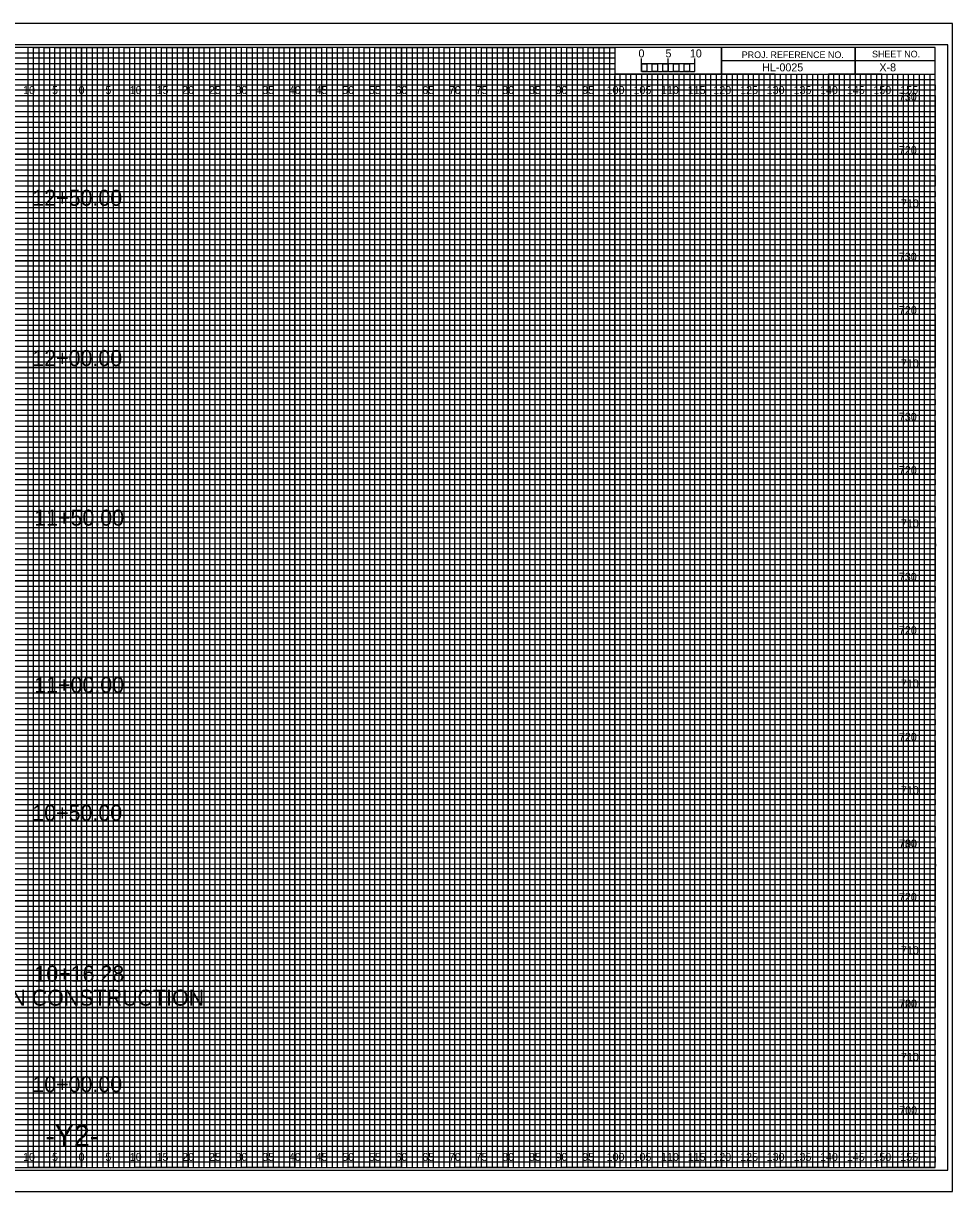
# Model space of a CAD drawing. Extents: x -13 to 323, y -5 to 654.
# Drawn here: x 149.1 to 323.3, y -4.5 to 214.5 of the extents above; entities that cross this region are included whole.
import ezdxf

# ---------------------------------------------------------------- set-up
doc = ezdxf.new("R2010")
doc.units = 0
for name, color, linetype in [('Exist CMT Pavement', 7, 'Continuous'), ('Exist Cross Section Cell', 7, 'Continuous'), ('Exist XS Center Line Elevation Label', 7, 'Continuous'), ('Exist XS Ground Line', 7, 'Continuous'), ('Prop CMT Pvmt Course 1', 7, 'Continuous'), ('Prop CMT Pvmt Course 1 Wedge', 7, 'Continuous'), ('Prop CMT Pvmt Course 2', 7, 'Continuous'), ('Prop CMT Pvmt Course 3', 7, 'Continuous'), ('Prop CMT Pvmt Surface', 7, 'Continuous'), ('Prop CMT Pvmt Surface Shoulder', 7, 'Continuous'), ('Prop CMT Pvmt Wedge Surface 1', 7, 'Continuous'), ('Prop CMT Shld Paved Course 1', 7, 'Continuous'), ('Prop CMT Shld Paved Course 2', 7, 'Continuous'), ('Prop CMT Shld Paved Course 3', 7, 'Continuous'), ('Prop CMT Slope Grass', 7, 'Continuous'), ('Prop CMT Subgrade Earthwork', 7, 'Continuous'), ('Scratch_Level_1', 7, 'Continuous')]:
    doc.layers.add(name, color=color, linetype=linetype)

msp = doc.modelspace()

# ---------------------------------------------------------------- linework, layer by layer
at = {"layer": 'Exist XS Center Line Elevation Label'}
for points in [[(145, 0), (155, 0), (155, 210), (165, 210), (165, 0), (175, 0), (175, 210), (185, 210), (185, 0), (195, 0), (195, 210), (205, 210), (205, 0), (215, 0), (215, 210), (225, 210), (225, 0), (235, 0), (235, 210), (245, 210), (245, 0), (255, 0), (255, 210), (259.93, 210), (260, 210), (260, 205), (264.99, 205), (264.99, 0), (275, 0), (275, 205), (285, 205), (285, 0), (295, 0), (295, 205), (305, 205), (305, 0), (315, 0), (315, 205)], [(0, 205), (275, 205)], [(0, 185), (320, 185), (320, 195), (0, 195)], [(0, 165), (320, 165), (320, 175), (0, 175)], [(0, 145), (320, 145), (320, 155), (0, 155)], [(0, 125), (320, 125), (320, 135), (0, 135)], [(0, 105), (320, 105), (320, 115), (0, 115)], [(0, 85), (320, 85), (320, 95), (0, 95)], [(0, 65), (320, 65), (320, 75), (0, 75)], [(0, 45), (320, 45), (320, 55), (0, 55)], [(0, 25), (320, 25), (320, 35), (0, 35)], [(0, 5), (320, 5), (320, 15), (0, 15)]]:
    msp.add_lwpolyline(points, dxfattribs=at)
at = {"layer": 'Exist XS Ground Line'}
for p, q in [((150, 210), (140, 210)), ((150, 0), (150, 210)), ((170, 210), (160, 210)), ((160, 210), (160, 0)), ((170, 0), (170, 210)), ((190, 210), (180, 210)), ((180, 210), (180, 0)), ((190, 0), (190, 210)), ((210, 210), (200, 210)), ((200, 210), (200, 0)), ((210, 0), (210, 210)), ((230, 210), (220, 210)), ((220, 210), (220, 0)), ((230, 0), (230, 210)), ((250, 210), (240, 210)), ((240, 210), (240, 0)), ((250, 0), (250, 210)), ((260, 210), (260, 0)), ((270, 0), (270, 205)), ((290, 205), (280, 205)), ((280, 205), (280, 0)), ((290, 0), (290, 205)), ((310, 205), (300, 205)), ((300, 205), (300, 0)), ((310, 0), (310, 205)), ((160, 0), (150, 0)), ((180, 0), (170, 0)), ((200, 0), (190, 0)), ((220, 0), (210, 0)), ((240, 0), (230, 0)), ((260, 0), (250, 0)), ((280, 0), (270, 0)), ((300, 0), (290, 0)), ((320, 0), (310, 0)), ((320, 0), (320, 0))]:
    msp.add_line(p, q, dxfattribs=at)
for points in [[(0, 200), (320, 200), (320, 190), (0, 190)], [(0, 180), (320, 180), (320, 170), (0, 170)], [(0, 160), (320, 160), (320, 150), (0, 150)], [(0, 140), (320, 140), (320, 130), (0, 130)], [(0, 120), (320, 120), (320, 110), (0, 110)], [(0, 100), (320, 100), (320, 90), (0, 90)], [(0, 80), (320, 80), (320, 70), (0, 70)], [(0, 60), (320, 60), (320, 50), (0, 50)], [(0, 40), (320, 40), (320, 30), (0, 30)], [(0, 20), (320, 20), (320, 10), (0, 10)]]:
    msp.add_lwpolyline(points, dxfattribs=at)
at = {"layer": 'Prop CMT Pvmt Course 2'}
msp.add_lwpolyline([(-13.4, -4.5), (323.3, -4.5), (323.3, 214.5), (-13.4, 214.5)], close=True, dxfattribs=at)
at = {"layer": 'Prop CMT Pvmt Course 3'}
msp.add_lwpolyline([(-10.8, -0.5), (322.4, -0.5), (322.4, 210.5), (-10.8, 210.5)], close=True, dxfattribs=at)
msp.add_lwpolyline([(-10.8, -0.5), (322.4, -0.5), (322.4, 210.5), (-10.8, 210.5)], close=True, dxfattribs=at)
at = {"layer": 'Prop CMT Pvmt Surface'}
for p, q in [((323.3, 214.5), (-13.4, 214.5)), ((323.3, 214.5), (-13.4, 214.5)), ((-13.4, -4.5), (323.3, -4.5)), ((-13.4, -4.5), (323.3, -4.5))]:
    msp.add_line(p, q, dxfattribs=at)
at = {"layer": 'Prop CMT Shld Paved Course 1'}
for p, q in [((305, 210), (305, 205)), ((305, 205), (305, 210)), ((280, 207.5), (280, 205)), ((320, 207.49), (280, 207.49)), ((280, 205), (320, 205))]:
    msp.add_line(p, q, dxfattribs=at)
for points in [[(320, 210), (0, 210), (0, 0), (320, 0)], [(280, 210), (260, 210), (260, 205.03), (280, 205.03)], [(320, 210), (280, 210), (280, 205), (320, 205)]]:
    msp.add_lwpolyline(points, close=True, dxfattribs=at)
at = {"layer": 'Prop CMT Shld Paved Course 2'}
for p, q in [((267, 205), (266.01, 205)), ((266.01, 205), (266.01, 0)), ((267, 0), (267, 205)), ((269, 205), (268, 205)), ((268, 205), (268, 0)), ((269, 0), (269, 205)), ((266.01, 0), (265, 0)), ((268, 0), (267, 0))]:
    msp.add_line(p, q, dxfattribs=at)
for points in [[(150, 0), (151, 0), (151, 210), (152, 210), (152, 0)], [(152, 0), (153, 0), (153, 210), (154, 210), (154, 0)], [(155, 0), (156, 0), (156, 210), (157, 210), (157, 0)], [(157, 0), (158, 0), (158, 210), (159, 210), (159, 0)], [(160, 0), (161, 0), (161, 210), (162, 210), (162, 0)], [(162, 0), (163, 0), (163, 210), (164, 210), (164, 0)], [(165, 0), (166, 0), (166, 210), (167, 210), (167, 0)], [(167, 0), (168, 0), (168, 210), (169, 210), (169, 0)], [(170, 0), (171, 0), (171, 210), (172, 210), (172, 0)], [(172, 0), (173, 0), (173, 210), (174, 210), (174, 0)], [(175, 0), (176, 0), (176, 210), (177, 210), (177, 0)], [(177, 0), (178, 0), (178, 210), (179, 210), (179, 0)], [(180, 0), (181, 0), (181, 210), (182, 210), (182, 0)], [(182, 0), (183, 0), (183, 210), (184, 210), (184, 0)], [(185, 0), (186, 0), (186, 210), (187, 210), (187, 0)], [(187, 0), (188, 0), (188, 210), (189, 210), (189, 0)], [(190, 0), (191, 0), (191, 210), (192, 210), (192, 0)], [(192, 0), (193, 0), (193, 210), (194, 210), (194, 0)], [(195, 0), (196, 0), (196, 210), (197, 210), (197, 0)], [(197, 0), (198, 0), (198, 210), (199, 210), (199, 0)], [(200, 0), (201, 0), (201, 210), (202, 210), (202, 0)], [(202, 0), (203, 0), (203, 210), (204, 210), (204, 0)], [(205, 0), (206, 0), (206, 210), (207, 210), (207, 0)], [(207, 0), (208, 0), (208, 210), (209, 210), (209, 0)], [(210, 0), (211, 0), (211, 210), (212, 210), (212, 0)], [(212, 0), (213, 0), (213, 210), (214, 210), (214, 0)], [(215, 0), (216, 0), (216, 210), (217, 210), (217, 0)], [(217, 0), (218, 0), (218, 210), (219, 210), (219, 0)], [(220, 0), (221, 0), (221, 210), (222, 210), (222, 0)], [(222, 0), (223, 0), (223, 210), (224, 210), (224, 0)], [(225, 0), (226, 0), (226, 210), (227, 210), (227, 0)], [(227, 0), (228, 0), (228, 210), (229, 210), (229, 0)], [(230, 0), (231, 0), (231, 210), (232, 210), (232, 0)], [(232, 0), (233, 0), (233, 210), (234, 210), (234, 0)], [(235, 0), (236, 0), (236, 210), (237, 210), (237, 0)], [(237, 0), (238, 0), (238, 210), (239, 210), (239, 0)], [(240, 0), (241, 0), (241, 210), (242, 210), (242, 0)], [(242, 0), (243, 0), (243, 210), (244, 210), (244, 0)], [(245, 0), (246, 0), (246, 210), (247, 210), (247, 0)], [(247, 0), (248, 0), (248, 210), (249, 210), (249, 0)], [(250, 0), (251, 0), (251, 210), (252, 210), (252, 0)], [(252, 0), (253, 0), (253, 210), (254, 210), (254, 0)], [(255, 0), (256, 0), (256, 210), (257, 210), (257, 0)], [(257, 0), (258, 0), (258, 210), (259, 210), (259, 0)], [(260, 0), (261, 0), (261, 205), (262.02, 205), (262.02, 0)], [(262, 0), (263, 0), (263, 205), (263.99, 205), (263.99, 0)], [(270, 0), (270.98, 0), (270.98, 205), (272, 205), (272, 0)], [(272, 0), (273, 0), (273, 205), (274.05, 205), (274.05, 0)], [(275, 0), (276, 0), (276, 205), (277, 205), (277, 0)], [(277, 0), (278, 0), (278, 205), (279, 205), (279, 0)], [(280, 0), (281, 0), (281, 205), (282, 205), (282, 0)], [(282, 0), (283, 0), (283, 205), (284, 205), (284, 0)], [(285, 0), (286, 0), (286, 205), (287, 205), (287, 0)], [(287, 0), (288, 0), (288, 205), (289, 205), (289, 0)], [(290, 0), (291, 0), (291, 205), (292, 205), (292, 0)], [(292, 0), (293, 0), (293, 205), (294, 205), (294, 0)], [(295, 0), (296, 0), (296, 205), (297, 205), (297, 0)], [(297, 0), (298, 0), (298, 205), (299, 205), (299, 0)], [(300, 0), (301, 0), (301, 205), (302, 205), (302, 0)], [(302, 0), (303, 0), (303, 205), (304, 205), (304, 0)], [(305, 0), (306, 0), (306, 205), (307, 205), (307, 0)], [(307, 0), (308, 0), (308, 205), (309, 205), (309, 0)], [(310, 0), (311, 0), (311, 205), (312, 205), (312, 0)], [(312, 0), (313, 0), (313, 205), (314, 205), (314, 0)], [(315, 0), (316, 0), (316, 205), (317, 205), (317, 0)], [(317, 0), (318, 0), (318, 205), (319, 205), (319, 0)]]:
    msp.add_lwpolyline(points, dxfattribs=at)
at = {"layer": 'Prop CMT Shld Paved Course 3'}
for p, q in [((265, 205.49), (265, 207.9)), ((265, 206.9), (265, 207.9)), ((270, 205.49), (270, 207.9)), ((275, 205.49), (275, 207.9)), ((275, 206.9), (275, 207.9))]:
    msp.add_line(p, q, dxfattribs=at)
for points in [[(275, 206.9), (265, 206.9), (265, 205.49), (275, 205.49)], [(265, 206.9), (266, 206.9), (266, 205.49), (265, 205.49)], [(267, 206.9), (268, 206.9), (268, 205.49), (267, 205.49)], [(269, 206.9), (270, 206.9), (270, 205.49), (269, 205.49)], [(271, 206.9), (272, 206.9), (272, 205.49), (271, 205.49)], [(273, 206.9), (274, 206.9), (274, 205.49), (273, 205.49)]]:
    msp.add_lwpolyline(points, close=True, dxfattribs=at)
at = {"layer": 'Prop CMT Subgrade Earthwork'}
for p, q in [((150, 0), (150, 210)), ((150, 0), (150, 210)), ((160, 0), (160, 210)), ((160, 0), (160, 210)), ((170, 0), (170, 210)), ((170, 0), (170, 210)), ((180, 0), (180, 210)), ((180, 0), (180, 210)), ((190, 0), (190, 210)), ((190, 0), (190, 210)), ((200, 0), (200, 210)), ((200, 0), (200, 210)), ((210, 0), (210, 210)), ((210, 0), (210, 210)), ((220, 0), (220, 210)), ((220, 0), (220, 210)), ((230, 0), (230, 210)), ((230, 0), (230, 210)), ((240, 0), (240, 210)), ((240, 0), (240, 210)), ((250, 0), (250, 210)), ((250, 0), (250, 210)), ((260, 0), (260, 204.69)), ((260, 0), (260, 204.69)), ((270, 0), (270, 204.69)), ((270, 0), (270, 204.69)), ((280, 0), (280, 204.69)), ((280, 0), (280, 204.69)), ((290, 0), (290, 204.69)), ((290, 0), (290, 204.69)), ((300, 0), (300, 204.69)), ((300, 0), (300, 204.69)), ((310, 0), (310, 204.69)), ((310, 0), (310, 204.69)), ((0, 200), (320, 200)), ((0, 200), (320, 200)), ((0, 190), (320, 190)), ((0, 190), (320, 190)), ((0, 180), (320, 180)), ((0, 180), (320, 180)), ((0, 170), (320, 170)), ((0, 170), (320, 170)), ((0, 160), (320, 160)), ((0, 160), (320, 160)), ((0, 150), (320, 150)), ((0, 150), (320, 150)), ((0, 140), (320, 140)), ((0, 140), (320, 140)), ((0, 130), (320, 130)), ((0, 130), (320, 130)), ((0, 120), (320, 120)), ((0, 120), (320, 120)), ((0, 110), (320, 110)), ((0, 110), (320, 110)), ((0, 100), (320, 100)), ((0, 100), (320, 100)), ((0, 90), (320, 90)), ((0, 90), (320, 90)), ((0, 80), (320, 80)), ((0, 80), (320, 80)), ((0, 70), (320, 70)), ((0, 70), (320, 70)), ((0, 60), (320, 60)), ((0, 60), (320, 60)), ((0, 50), (320, 50)), ((0, 50), (320, 50)), ((0, 40), (320, 40)), ((0, 40), (320, 40)), ((0, 30), (320, 30)), ((0, 30), (320, 30)), ((0, 20), (320, 20)), ((0, 20), (320, 20)), ((0, 10), (320, 10)), ((0, 10), (320, 10))]:
    msp.add_line(p, q, dxfattribs=at)
at = {"layer": 'Scratch_Level_1'}
for p, q in [((0, 209), (260, 209)), ((260, 209), (260, 207.98)), ((260, 207.98), (0, 207.98)), ((0, 207), (260, 207)), ((260, 205.89), (0, 205.89)), ((260, 207), (260, 205.89)), ((0, 204), (320, 204))]:
    msp.add_line(p, q, dxfattribs=at)
for points in [[(0, 203), (270, 203), (320, 203), (320, 202), (0, 202)], [(0, 201), (320, 201), (320, 199), (0, 199)], [(0, 198), (320, 198), (320, 197), (0, 196.98)], [(0, 196), (320, 196), (320, 194), (0, 194)], [(0, 193), (320, 193), (320, 192), (0, 192)], [(0, 191), (320, 191), (320, 189), (0, 189)], [(0, 188), (320, 188), (320, 187), (0, 187)], [(0, 186), (320, 186), (320, 184), (0, 184)], [(0, 183), (320, 183), (320, 182), (0, 182)], [(0, 181), (320, 181), (320, 179), (0, 179)], [(0, 178), (320, 178), (320, 177), (0, 177)], [(0, 176), (320, 176), (320, 173.95), (320, 173), (320, 172), (0, 172)], [(0, 174), (320, 174), (320, 173), (0, 173)], [(0, 171), (320, 171), (320, 169), (0, 169.03)], [(0, 169.03), (320, 169), (320, 168), (0, 168)], [(0, 167), (320, 167), (320, 166), (0, 166)], [(0, 164), (320, 164), (320, 163), (0, 163)], [(0, 162), (320, 162), (320, 161), (0, 161)], [(-0.07, 158.89), (320, 158.89), (320, 157.88), (-0.07, 157.88)], [(0, 157), (320, 157), (320, 156), (0, 156)], [(0, 154), (320, 154), (320, 153), (0, 153)], [(0, 152), (320, 152), (320, 151), (0, 151)], [(0, 149), (320, 149), (320, 148), (0, 148)], [(0, 147), (320, 147), (320, 146), (0, 146)], [(0, 144), (320, 144), (320, 143), (0, 143)], [(0, 142), (320, 142), (320, 141), (0, 141)], [(0, 139), (320, 139), (319.99, 137.98), (0, 138)], [(0, 137), (320, 137), (320, 136), (0, 136)], [(0, 134), (320, 134), (320, 133), (0, 133)], [(0, 132), (320, 132), (320, 131), (0, 131)], [(0, 129), (320, 129), (320, 128), (0, 128)], [(0, 127), (320, 127), (320, 126), (0, 126)], [(0, 124), (320, 124), (320, 123), (0, 123)], [(0, 122), (320, 122), (320, 121), (0, 121)], [(0, 119), (320, 119), (320, 118), (0, 118)], [(0, 116.99), (320.07, 116.91), (320, 116), (0, 116)], [(0, 114), (320, 114), (320, 113), (0, 113)], [(0, 112), (320, 112), (320, 111), (0, 111)], [(0, 109), (320, 109), (320, 108), (0, 108)], [(0, 107), (320, 107), (320, 106), (0, 106)], [(0, 104), (320, 104), (320, 103), (0, 103)], [(0, 102), (320, 102), (320, 101), (0, 101)], [(0, 99), (320, 99), (320, 98), (0, 98)], [(0, 97), (320, 97), (320, 96), (0, 96)], [(0, 94), (320, 94), (320, 93), (0, 93)], [(0, 92), (320, 92), (320, 91), (0, 91)], [(0, 89), (320, 89), (320, 88), (0, 88)], [(0, 87), (320, 87), (320, 86), (0, 86)], [(0, 84), (320, 84), (320, 83), (0, 83)], [(0, 82), (320, 82), (320, 81), (0, 81)], [(0, 79), (320, 79), (319.99, 77.98), (0, 78)], [(0, 77), (320, 77), (320, 76), (0, 76)], [(0, 74), (320, 74), (320, 73), (0, 73)], [(0, 72), (320, 72), (320, 71), (0, 71)], [(0, 69), (320, 69), (320, 68), (0, 68)], [(0, 67), (320, 67), (320, 66), (0, 66)], [(0, 64), (320, 64), (320, 63), (0, 63)], [(0, 62), (320, 62), (320, 61), (0, 61)], [(0, 59), (320, 59), (320, 58), (0, 58)], [(0, 56.99), (320.07, 56.91), (320, 56), (0, 56)], [(0, 54), (320, 54), (320, 53), (0, 53)], [(0, 52), (320, 52), (320, 51), (0, 51)], [(0, 49), (320, 49), (320, 48), (0, 48)], [(0, 47), (320, 47), (320, 46), (0, 46)], [(0, 44), (320, 44), (320, 43), (0, 43)], [(0, 42), (320, 42), (320, 41), (0, 41)], [(0, 39), (320, 39), (320, 38), (0, 38)], [(0, 37), (320, 37), (320, 36), (0, 36)], [(0, 34), (320, 34), (320, 33), (0, 33)], [(0, 32), (320, 32), (320, 31), (0, 31)], [(0, 29), (320, 29), (320, 28), (0, 28)], [(0, 27), (320, 27), (320, 26), (0, 26)], [(0, 24), (320, 24), (320, 23), (0, 23)], [(0, 22), (320, 22), (320, 21), (0, 21)], [(0, 19), (320, 19), (320, 18), (0, 18)], [(0, 17), (320, 17), (320, 16), (0, 16)], [(0, 14), (320, 14), (320, 13), (0, 13)], [(0, 12), (320, 12), (320, 11), (0, 11)], [(0, 9), (320, 9), (320, 8), (0, 8)], [(0, 7), (320, 7), (320, 6), (0, 6)], [(0, 4), (320, 4), (320, 3), (0, 3)], [(0, 2), (320, 2), (320, 1), (0, 1)]]:
    msp.add_lwpolyline(points, dxfattribs=at)

# ---------------------------------------------------------------- texts
at = {"layer": 'Exist CMT Pavement'}
msp.add_text('-Y2-', height=4, dxfattribs=at).set_placement((153.21, 4))
at = {"layer": 'Exist Cross Section Cell'}
for s, p in [('10', (149.04, 201.25)), ('5', (154.47, 201.25)), ('0', (159.45, 201.25)), ('0', (159.45, 201.25)), ('5', (164.47, 201.25)), ('10', (169.04, 201.25)), ('15', (174.06, 201.25)), ('20', (178.86, 201.25)), ('25', (183.88, 201.25)), ('30', (188.86, 201.25)), ('35', (193.88, 201.25)), ('40', (198.86, 201.25)), ('45', (203.88, 201.25)), ('50', (208.86, 201.25)), ('55', (213.88, 201.25)), ('60', (218.86, 201.25)), ('65', (223.88, 201.25)), ('70', (228.86, 201.25)), ('75', (233.88, 201.25)), ('80', (238.86, 201.25)), ('85', (243.88, 201.25)), ('90', (248.86, 201.25)), ('95', (253.88, 201.25)), ('100', (258.44, 201.25)), ('105', (263.47, 201.25)), ('110', (268.62, 201.25)), ('115', (273.65, 201.25)), ('120', (278.44, 201.25)), ('125', (283.47, 201.25)), ('130', (288.44, 201.25)), ('135', (293.47, 201.25)), ('140', (298.44, 201.25)), ('145', (303.47, 201.25)), ('150', (308.44, 201.25)), ('155', (313.47, 201.25)), ('10', (149.04, 1.25)), ('5', (154.47, 1.25)), ('0', (159.45, 1.25)), ('0', (159.45, 1.25)), ('5', (164.47, 1.25)), ('10', (169.04, 1.25)), ('15', (174.06, 1.25)), ('20', (178.86, 1.25)), ('25', (183.88, 1.25)), ('30', (188.86, 1.25)), ('35', (193.88, 1.25)), ('40', (198.86, 1.25)), ('45', (203.88, 1.25)), ('50', (208.86, 1.25)), ('55', (213.88, 1.25)), ('60', (218.86, 1.25)), ('65', (223.88, 1.25)), ('70', (228.86, 1.25)), ('75', (233.88, 1.25)), ('80', (238.86, 1.25)), ('85', (243.88, 1.25)), ('90', (248.86, 1.25)), ('95', (253.88, 1.25)), ('100', (258.44, 1.25)), ('105', (263.47, 1.25)), ('110', (268.62, 1.25)), ('115', (273.65, 1.25)), ('120', (278.44, 1.25)), ('125', (283.47, 1.25)), ('130', (288.44, 1.25)), ('135', (293.47, 1.25)), ('140', (298.44, 1.25)), ('145', (303.47, 1.25)), ('150', (308.44, 1.25)), ('155', (313.47, 1.25))]:
    msp.add_text(s, height=1.5, dxfattribs=at).set_placement(p)
at = {"layer": 'Prop CMT Pvmt Course 1'}
for s, p in [('12+50.00', (150.77, 180.3)), ('12+00.00', (150.77, 150.26)), ('11+50.00', (151.13, 120.34)), ('11+00.00', (151.13, 89)), ('10+50.00', (150.77, 65.01)), ('10+16.28', (151.16, 34.86)), ('BEGIN CONSTRUCTION', (137.07, 30.36)), ('10+00.00', (150.77, 14.15))]:
    msp.add_text(s, height=3, dxfattribs=at).set_placement(p)
at = {"layer": 'Prop CMT Pvmt Course 1 Wedge'}
msp.add_text('HL-0025', height=1.5, dxfattribs=at).set_placement((287.6, 205.5))
at = {"layer": 'Prop CMT Pvmt Surface Shoulder'}
for s, p in [('730', (313.22, 200)), ('720', (313.23, 190)), ('710', (313.61, 180)), ('730', (313.22, 170)), ('720', (313.23, 160)), ('710', (313.61, 150)), ('730', (313.22, 140)), ('720', (313.23, 130)), ('710', (313.61, 120)), ('730', (313.22, 110)), ('720', (313.23, 100)), ('710', (313.61, 90)), ('720', (313.23, 80)), ('710', (313.61, 70)), ('730', (313.22, 60)), ('700', (313.28, 60)), ('720', (313.23, 50)), ('710', (313.61, 40)), ('720', (313.23, 30)), ('700', (313.28, 30)), ('710', (313.61, 20)), ('700', (313.28, 10))]:
    msp.add_text(s, height=1.5, dxfattribs=at).set_placement(p)
at = {"layer": 'Prop CMT Pvmt Wedge Surface 1'}
for s, p in [('5', (269.47, 208.12)), ('10', (274.04, 208.12))]:
    msp.add_text(s, height=1.5, dxfattribs=at).set_placement(p)
at = {"layer": 'Prop CMT Shld Paved Course 1'}
for s, p in [('PROJ. REFERENCE NO.', (283.77, 207.99)), ('SHEET NO.', (308.19, 208.12))]:
    msp.add_text(s, height=1.25, dxfattribs=at).set_placement(p)
at = {"layer": 'Prop CMT Shld Paved Course 3'}
msp.add_text('0', height=1.5, dxfattribs=at).set_placement((264.41, 208.12))
at = {"layer": 'Prop CMT Slope Grass'}
msp.add_text('X-8', height=1.5, dxfattribs=at).set_placement((309.57, 205.5))

doc.saveas('drawing.dxf')
